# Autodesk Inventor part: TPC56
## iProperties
Shininess: 64.0
Length Units: 11272
Angle Units: 11279
Time Units: 11290
Mass Units: 11286
Length Display Precision: 3
Angle Display Precision: 2
Compacted: True
Part Number: TPC56
Document SubType Name: Modeling
Created: 2004-08
Designer: Lori
Manufacturer: Standard
Standards Organization: Custom
Density: 0.0
Volumn: 0.0
Area: 0.0
PropertySet Name: Model Information
Control State: 0
Master: False
Checked Out: False
Author: Lori
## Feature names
1. Base1
